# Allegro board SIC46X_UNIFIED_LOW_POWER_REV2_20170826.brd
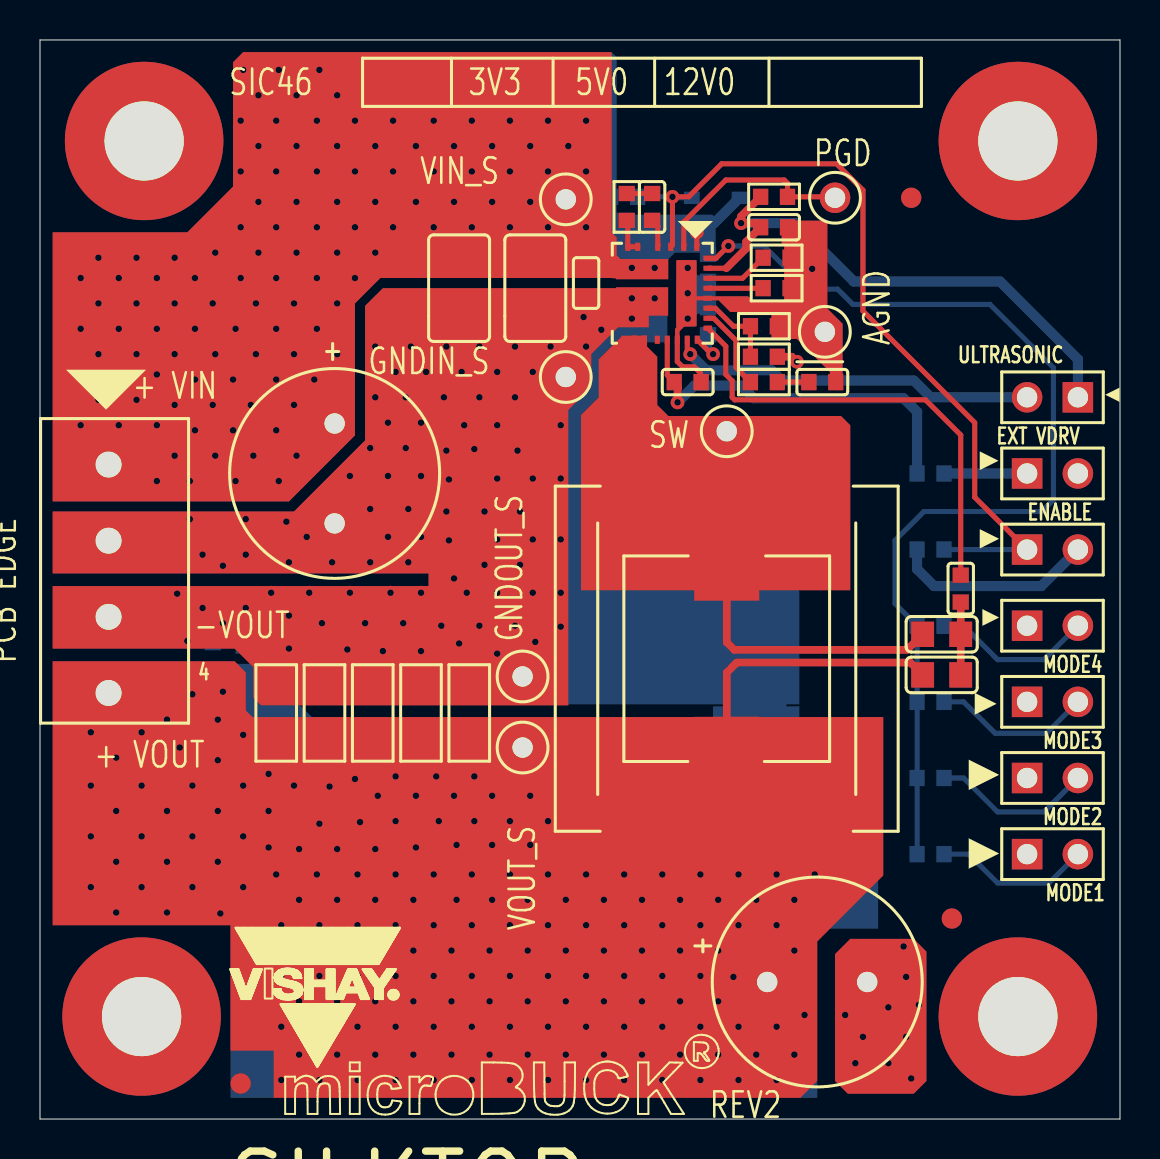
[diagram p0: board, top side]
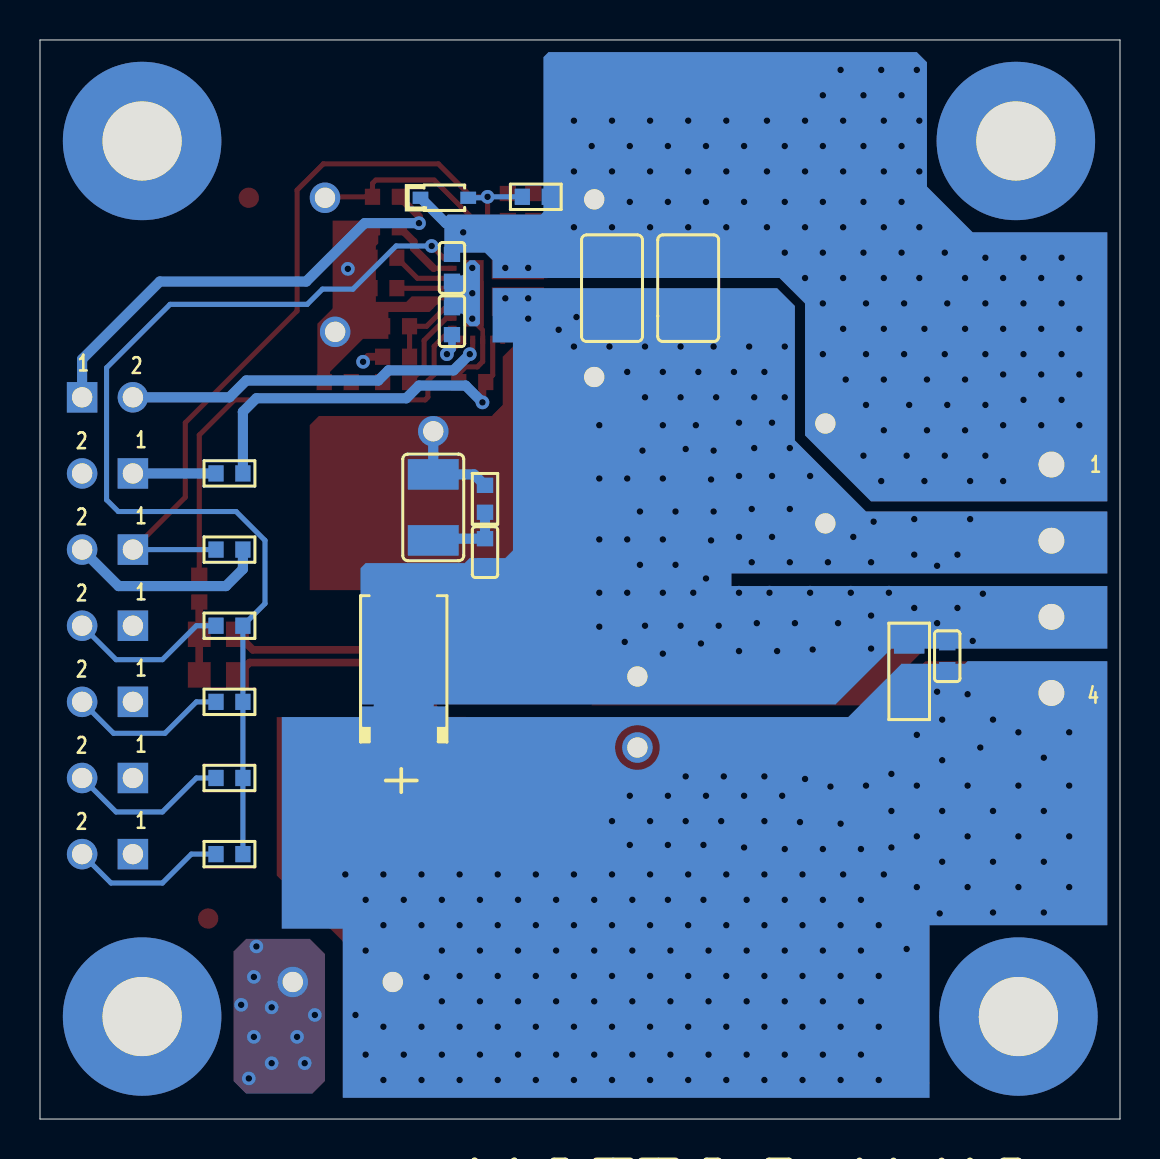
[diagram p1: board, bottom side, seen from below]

Outline 54 x 54 mm; copper layers: TOP, INNER_LAYER2, INNER_LAYER3, BOTTOM. Coordinates in mm from the lower left corner of the outline.
Outline path: 0,54 0,0 54,0 54,54 0,54

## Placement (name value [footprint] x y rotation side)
C1  0.1uF  [C0603]  30.61 45.64 270 top
C2  0.1uF  [C0603]  33.4 42.59 270 bottom
C3  1uF  [C0603]  36.7 44.63 180 top
C4  2.2uF  [C1210]  21.59 41.58 90 bottom
C5  2.2uF  [C1210]  24.77 41.58 90 top
C6  2.2uF  [C1210]  20.95 41.58 90 top
C7  2.2uF  [C1210]  25.4 41.58 90 bottom
C8  0.1uF  [C0603]  27.3 41.83 270 top
C9  1nF  [C0603]  39.12 36.88 180 top
C10  22nF  [C0603]  33.4 39.93 90 bottom
C11  4.7uF  [C0603]  32.38 36.88 180 top
C12  2.2nF  [C0603]  46.04 26.54 270 top
C13  22nF  [C0805]  45.09 22.23 180 top
C14  0.1uF  [C0603]  8.64 23.16 270 bottom
C15  22uF  [C1206]  19.05 20.32 270 top
C16  22uF  [C1206]  14.22 20.32 270 top
C17  22uF  [C1206]  10.54 22.4 270 bottom
C18  22uF  [C1206]  21.46 20.32 270 top
C19  22uF  [C1206]  11.81 20.32 270 top
C20  22uF  [C1206]  16.64 20.32 270 top
C21  DNP  [C0603]  31.75 28.37 270 bottom
C22  100uF 63V  [MAL215058101E3]  14.73 32.31 270 top
C23  470u, 2V  [T_D27_7343]  35.81 22.53 90 bottom
C24  100uF 63V  [MAL215058101E3]  38.86 6.86 0 top
D1  DNP  [BZX384C3V3]  33.78 46.1 0 bottom
J1  JUMPER  [22-28-4023]  49.35 13.26 0 top
J2  JUMPER  [22-28-4023]  49.35 17.07 0 top
J3  JUMPER  [22-28-4023]  49.35 20.88 0 top
J4  JUMPER  [22-28-4023]  49.35 24.69 0 top
J5  CON4  [20020327-D041B01LF]  3.43 32.75 270 top
J6  PGD  [5002]  39.75 46.1 0 top
J7  EN  [22-28-4023]  49.35 32.31 0 top
J8  JUMPER  [22-28-4023]  51.89 36.12 180 top
J9  EN  [22-28-4023]  49.35 28.5 0 top
J10  GND  [5002]  39.24 39.39 0 top
L1  DNP  [IHLP-4040]  34.34 23.04 90 top
L2  4.7uH  [IHLP-5050]  34.34 23.04 90 top
L3  DNP  [IHLP-6767]  34.34 23.04 90 top
NOREF  -  []  0.03 42.45 0 top
NOREF#2  -  []  4.51 -8.21 0 top
NOREF#3  -  []  117.09 -44.06 0 top
NOREF#4  -  []  58.78 -20.91 90 top
NOREF#5  -  []  54 0 90 top
NOREF#6  -  []  182.52 -46.31 90 top
NOREF#7  -  []  107.08 -20.91 90 top
NOREF#8  -  []  161.42 70.03 0 top
NOREF#9  -  []  56.01 70.03 0 top
NOREF#10  -  []  10.86 -32.97 0 top
NOREF#11  -  []  10.86 41.32 0 top
NOREF#12  -  []  161.42 70.03 90 top
NOREF#13  -  []  21.21 -21.41 90 top
NOREF#14  -  []  68.98 71.53 90 top
NOREF#15  -  []  0 54 0 top
NOREF#16  -  []  26.86 -26.06 90 top
NOREF#17  -  []  133.48 70.03 0 top
NOREF#18  -  []  17.21 -8.21 0 top
NOREF#19  -  []  -1.14 48.24 0 top
NOREF#20  -  []  10.86 16.56 0 top
NOREF#21  -  []  119.33 -10.49 0 top
NOREF#22  -  []  3.43 28.94 90 top
NOREF#23  -  []  68.98 73.03 0 top
NOREF#24  -  []  134.22 -28.53 90 top
NOREF#25  -  []  198.91 -27.76 0 top
NOREF#26  -  [unnamed#2]  43.56 46.1 0 top
NOREF#27  -  []  -1.14 -26.06 0 top
NOREF#28  -  []  132.48 73.03 0 top
NOREF#29  -  []  147.45 70.03 0 top
NOREF#30  -  []  146.45 71.53 90 top
NOREF#31  -  []  17.21 16.56 0 top
NOREF#32  -  []  69.98 70.03 0 top
NOREF#33  -  []  182.52 -31.07 90 top
NOREF#34  -  []  4.51 16.56 0 top
NOREF#35  -  []  118.49 -0.84 90 top
NOREF#36  -  []  56.01 70.03 90 top
NOREF#37  -  []  -1.14 23.47 0 top
NOREF#38  -  []  21.21 28.12 90 top
NOREF#39  -  []  26.86 23.47 90 top
NOREF#40  -  []  133.48 70.03 90 top
NOREF#41  -  []  134.22 -46.31 90 top
NOREF#42  -  []  15.27 35.05 90 top
NOREF#43  -  []  69.98 70.03 90 top
NOREF#44  -  []  107.08 -28.53 90 top
NOREF#45  -  []  -1.14 -1.29 0 top
NOREF#46  -  []  160.42 73.03 0 top
NOREF#47  -  []  4.51 41.32 0 top
NOREF#48  -  []  56.83 15.65 0 top
NOREF#49  -  []  146.45 73.03 0 top
NOREF#50  -  []  58.78 -31.07 90 top
NOREF#51  -  []  134.22 -28.53 90 top
NOREF#52  -  [unnamed#2]  5.08 5.13 0 top
NOREF#53  -  []  132.48 71.53 90 top
NOREF#54  -  [unnamed#2]  5.21 48.94 0 top
NOREF#55  -  []  107.08 -3.13 90 top
NOREF#56  -  []  107.08 -38.69 90 top
NOREF#57  -  []  21.21 52.89 90 top
NOREF#58  -  []  17.21 41.32 0 top
NOREF#59  -  []  147.45 70.03 90 top
NOREF#60  -  []  107.08 -13.29 90 top
NOREF#61  -  []  21.21 -46.17 90 top
NOREF#62  -  []  134.22 -13.29 90 top
NOREF#63  -  [unnamed#2]  48.9 5.13 0 top
NOREF#64  -  []  55.01 71.53 90 top
NOREF#65  -  []  58.78 -46.31 0 top
NOREF#66  -  []  182.52 -20.91 90 top
NOREF#67  -  []  26.86 -1.29 90 top
NOREF#68  -  []  114.81 -1.72 0 top
NOREF#69  -  []  118.15 -13.87 0 top
NOREF#70  -  []  -69.09 -66.37 0 top
NOREF#71  -  []  3.43 32.75 90 top
NOREF#72  -  []  10.86 66.09 0 top
NOREF#73  -  []  134.22 -20.91 90 top
NOREF#74  -  []  17.21 66.09 0 top
NOREF#75  -  []  -37.59 -32.57 0 top
NOREF#76  -  []  17.21 -32.97 0 top
NOREF#77  -  []  58.78 -46.31 90 top
NOREF#78  -  []  4.51 66.09 0 top
NOREF#79  -  []  193.14 -38.2 0 top
NOREF#80  -  [unnamed#2]  45.59 10.03 0 top
NOREF#81  -  []  62.61 26.08 0 top
NOREF#82  -  []  0.03 35.05 0 top
NOREF#83  -  [unnamed#2]  48.9 48.94 0 top
NOREF#84  -  []  4.51 -32.97 0 top
NOREF#85  -  []  10.86 -8.21 0 top
NOREF#86  -  []  26.86 -50.82 90 top
NOREF#87  -  []  120.78 -43.18 90 top
NOREF#88  -  []  26.86 48.24 90 top
NOREF#89  -  []  160.42 71.53 90 top
NOREF#90  -  []  107.08 -20.91 90 top
NOREF#91  -  []  -1.14 -50.82 0 top
NOREF#92  -  []  55.01 73.03 0 top
NOREF#93  -  []  134.22 -38.69 90 top
NOREF#94  -  []  134.22 4.49 0 top
NOREF#95  -  []  21.21 3.36 90 top
NOREF#96  -  [unnamed#2]  10.03 1.78 0 top
R1  102K  [R0603]  36.7 46.15 180 top
R2  3.3  [R0603]  29.34 45.64 90 top
R3  560K  [R0603]  29.21 46.15 0 bottom
R4  53.6K  [R0603]  36.83 43.1 180 top
R5  2K  [R0603]  44.53 13.26 0 bottom
R6  301K  [R0603]  44.53 17.07 0 bottom
R7  499K  [R0603]  44.53 20.88 0 bottom
R8  1M  [R0603]  44.53 24.69 0 bottom
R9  53.6K  [R0603]  36.83 41.58 180 top
R10  10K  [R0603]  36.2 39.67 180 top
R11  19.6K  [R0603]  36.2 36.88 180 top
R12  52.3K  [R0603]  36.2 38.15 0 top
R14  DNP  [R0603]  44.53 32.31 180 bottom
R15  DNP  [R0805]  45.09 24.26 180 top
R16  DNP  [R0603]  31.75 31.04 270 bottom
R16A  DNP  [R1210]  34.34 30.61 270 bottom
R17  DNP  [R0603]  44.53 28.5 0 bottom
TP1  test point  [5002]  26.29 46.02 0 top
TP2  test point  [5002]  26.29 37.13 0 top
TP3  test point  [5002]  24.13 18.59 0 top
TP4  test point  [5002]  24.13 22.15 90 top
TP11  5002  [PAD040_060_SQ]  34.34 34.42 0 top
U1  SiC46X  [5MMX5MM]  31.11 41.32 270 top

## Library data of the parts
C1-C21 = CAP NP
C22 C24 = CAP POL
C23 = CAP, TA-P,V,470u, 2V_0: User Part Number: PN; Tolerance: TOL
D1 = DIODE ZENER
J1-J4 J8 = JUMPER
J5 = HEADER 4
J6 J10 = HEADER 1
J7 J9 = HEADER 2
L1-L3 = IND
R1-R12 R14-R16 R16A R17 = RESISTOR
TP1-TP4 = TEST POINT
TP11 = TP_0
U1 = SiC462CD-T1-GE3_32

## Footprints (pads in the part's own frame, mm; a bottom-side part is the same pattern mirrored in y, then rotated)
5MMX5MM
  rect 0.406x0.254 smd: 1(-2.325,1.725) 2(-2.325,1.075) 3(-2.325,0.425) 4(-2.325,-0.225) 5(-2.325,-1.225) 6(-2.325,-1.725) 13(2.325,-1.4) 14(2.325,-0.9) 15(2.325,-0.25) 16(2.325,0.25) 17(2.325,0.75) 18(2.325,1.25) 19(2.325,1.75)
  rect 0.254x0.432 smd: 7(-1.525,-2.275) 8(-0.875,-2.275) 9(0.25,-2.275) 10(0.75,-2.275) 11(1.25,-2.275) 20(1.75,2.275) 21(1.25,2.275) 22(0.75,2.275) 23(0.25,2.275) 24(-0.25,2.275) 25(-0.75,2.275) 26(-1.25,2.275) 27(-1.75,2.275)
  rect 0.406x1.27 smd: 12(2.325,-1.408)
  rect 3.302x1.016 smd: 28(0,1.208)
  rect 1.016x2.616 smd: 29(-1.208,-1.008)
  custom 0.5x0.5 smd: 30(0.7,-1.008)
22-28-4023
  rect 1.524x1.524 hole 1.016: 1(0,0)
  round 1.524 hole 1.016: 2(2.54,0)
5002
  round 1.524 hole 1.016: 1(0,0)
20020327-D041B01LF
  rect 2.057x2.057 hole 1.295: 1(0,0)
  round 2.057 hole 1.295: 2(3.81,0) 3(7.62,0) 4(11.43,0)
BZX384C3V3
  rect 0.787x0.61 smd: 1(1.194,0) 2(-1.194,0)
C0603
  rect 0.762x0.813 smd: 1(-0.673,0) 2(0.673,0)
C0805
  rect 1.143x1.27 smd: 1(-0.953,0) 2(0.953,0)
C1206
  rect 1.27x1.524 smd: 1(-1.524,0) 2(1.524,0)
C1210
  rect 1.524x2.54 smd: 1(-1.651,0) 2(1.651,0)
IHLP-4040
  rect 3.124x3.251 smd: 1(-4.47,0) 2(4.47,0)
IHLP-5050
  rect 3.175x3.251 smd: 1(-5.715,0) 2(5.715,0)
IHLP-6767
  rect 3.81x12.319 smd: 1(-8.077,0) 2(8.077,0)
MAL215058101E3
  rect 1.524x1.524 hole 1.016: 1(-2.5,0)
  round 1.524 hole 1.016: 2(2.5,0)
PAD040_060_SQ
  round 1.524 hole 1.016: 1(0,0)
R0603
  rect 0.762x0.813 smd: 1(-0.673,0) 2(0.673,0)
R0805
  rect 1.143x1.27 smd: 1(-0.953,0) 2(0.953,0)
R1210
  rect 1.524x2.54 smd: 1(-1.651,0) 2(1.651,0)
T_D27_7343
  rect 2.134x2.997 smd: 1(-3.429,0) 3(3.429,0)
  custom 1.079x1.079 smd: 2(0,0)
unnamed#2
  round 1.016 smd: 1(0,0)

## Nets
GND: C4.1 C5.1 C6.1 C7.1 C8.2 C14.1 C15.1 C16.1 C17.1 C18.1 C19.1 C20.1 C21.2 C22.2 C23.2 C23.3 C24.2 J5.2 J5.3 J7.2 TP2.1 TP4.1 U1.9(PGND1) U1.10(PGND2) U1.11(PGND3) U1.30(PGND-PAD)
GND_SIGNAL: C2.2 C3.1 C9.1 C10.2 C11.1 J1.1 J2.1 J3.1 J4.1 J9.2 J10.1 R4.1 R9.1 R10.1 R17.1 U1.17(CDRV_RTN) U1.23(AGND) U1.28(AGND-PAD)
VDD: C3.2 J8.1 R1.2 U1.26(VDD)
VIN: C2.1 C4.2 C5.2 C6.2 C7.2 C8.1 C22.1 D1.1(CATHODE) J5.1 R3.1 TP1.1 U1.1(VCIN) U1.7(VIN1) U1.8(VIN2) U1.29(VIN-PAD)
BOOT: C1.2 U1.4(BOOT)
COMP: R11.2 U1.21(COMP)
ENABLE: D1.2(ANODE) J9.1 R3.2 R17.2 U1.3(EN)
FSW: R9.2 U1.24(FSW)
ILIM: R4.2 U1.25(ILIMIT)
MODE: R5.1 R6.1 R7.1 R8.1 U1.27(MODE)
PGD: J6.1 R1.1 U1.2(PGOOD)
SS: C10.1 U1.19(SS)
SW: L1.2(B) L2.2(B) L3.2(B) R15.2 R16.1 R16A.1 TP11.1 U1.12(SW1) U1.13(SW2) U1.14(SW3)
ULTRASONIC: J8.2 U1.18(ULTRASONIC)
VDRV: C11.2 R14.2 U1.16(VDRV)
VDRV_IN: J7.1 R14.1
VFB: R10.2 R12.1 U1.22(VFB)
VO: C13.2 C14.2 C15.2 C16.2 C17.2 C18.2 C19.2 C20.2 C23.1 C24.1 J5.4 L1.1(A) L2.1(A) L3.1(A) R12.2 TP3.1
N16770186: R2.1 U1.5(PHASE1) U1.6(PHASE2)
N16770229: C1.1 R2.2
N16771868: C9.2 R11.1
N16772198: J1.2 R5.2
N16772202: J2.2 R6.2
N16772206: J3.2 R7.2
N16812890: C21.1 R16.2 R16A.2
N16829136: J4.2 R8.2
N16842327: C12.1 U1.20(VSNS)
N16874863: C12.2 C13.1 R15.1

Pads without a net: NOREF#26 1; NOREF#52 1; NOREF#54 1; NOREF#63 1; NOREF#80 1; NOREF#83 1; NOREF#96 1; U1 15

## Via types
v1: diameter 0.686, hole 0.33, TOP to BOTTOM, 418 vias

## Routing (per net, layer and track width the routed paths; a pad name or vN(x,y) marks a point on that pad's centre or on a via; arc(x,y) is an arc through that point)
GND:
  vias: v1(6.86,26.29) v1(7.37,23.92) v1(7.49,30.02) v1(8.13,28.24) v1(8.13,25.58) v1(9.14,27.69) v1(9.14,24.81) v1(10.29,30.02) v1(10.29,28.24) v1(10.29,25.58) v1(11.56,26.34) v1(12.32,29.89) v1(12.45,27.86) v1(12.45,25.19) v1(12.45,23.54) v1(13.34,29.13) v1(13.46,26.34) v1(14.1,24.81) v1(14.61,27.86) v1(15.37,23.5) v1(15.49,32.18) v1(15.49,26.34) v1(16.26,24.81) v1(16.51,33.58) v1(16.51,30.53) v1(16.51,27.86) v1(16.76,38.66) v1(16.76,36.12) v1(17.14,23.42) v1(17.4,34.85) v1(17.4,32.18) v1(17.4,29.13) v1(17.53,26.34) v1(17.78,37.39) v1(18.16,24.81) v1(18.29,36.12) v1(18.29,33.58) v1(18.41,30.53) v1(18.41,27.86) v1(18.54,38.66) v1(19.05,34.85) v1(19.05,32.18) v1(19.05,29.13) v1(19.05,26.34) v1(19.05,23.42) v1(19.3,37.39) v1(20.07,24.69) v1(20.19,36.12) v1(20.32,38.66) v1(20.32,33.45) v1(20.32,30.4) v1(20.45,32) v1(20.45,28.96) v1(20.7,27.05) v1(20.95,23.8) v1(21.08,37.39) v1(21.21,34.72) v1(21.34,26.34) v1(21.72,33.53) v1(21.97,38.66) v1(21.97,36.12) v1(21.97,24.69) v1(22.23,30.4) v1(22.23,27.73) v1(22.86,37.39) v1(22.86,34.72) v1(22.86,32.05) v1(22.86,29) v1(22.86,26.34) v1(22.86,23.29) v1(23.75,38.66) v1(23.75,36.12) v1(23.75,24.69) v1(23.88,33.45) v1(24,30.4) v1(24,27.73) v1(24.64,37.39) v1(24.64,32.05) v1(24.64,29) v1(24.64,26.34) v1(24.77,23.88) v1(25.53,38.66) v1(26.04,34.72) v1(26.04,32.05) v1(26.04,29) v1(26.04,26.34) v1(26.04,24.64) v1(27.18,40.13) v1(27.3,38.66) v1(28.07,39.5) v1(29.59,41.07) v1(29.59,40.05) v1(30.73,41.07) v1(40.26,5.21) v1(40.77,2.79) v1(41.15,4.11) v1(42.42,5.59) v1(42.42,2.79) v1(43.18,8.64) v1(43.31,7.11) v1(43.31,4.11) v1(43.56,2.03) v1(43.94,5.71)
GND_SIGNAL: length 13.1
  TOP w0.254: U1.17 31.87,37.91 32.13,37.64 32.72,37.64 33.02,37.34 33.02,36.92 C11.1
  BOTTOM w0.508: J9.2 50.07,26.67 44.7,26.67 43.86,27.52 R17.1
  vias: v1(32.38,42.59) v1(32.38,41.32) v1(32.38,40.05) v1(38.61,42.55)
VDD: length 28
  TOP w0.254: 34.32,42.57 U1.26
  TOP w0.381: 34.32,42.57 35.31,43.56 35.31,43.9 C3.2 35.82,44.83 v1(35.05,44.83) 35.05,45.17 R1.2
  BOTTOM w0.508: J8.1 51.89,38.02 48.01,41.91 40.69,41.91 37.77,44.83 v1(35.05,44.83)
VIN: length 2.7
  TOP w0.254: U1.1 v1(32.84,44.37)
  BOTTOM w0.508: D1.1 33.71,44.83 33.53,44.83
  vias: v1(2.03,42.09) v1(2.03,39.55) v1(2.03,37.26) v1(2.03,34.72) v1(2.92,43.1) v1(2.92,40.82) v1(2.92,38.28) v1(2.92,35.99) v1(3.94,42.09) v1(3.94,39.55) v1(3.94,37.26) v1(3.94,34.72) v1(4.83,43.1) v1(4.83,40.82) v1(4.83,38.28) v1(4.83,35.99) v1(5.84,42.09) v1(5.84,39.55) v1(5.84,37.26) v1(5.84,34.72) v1(5.84,31.93) v1(6.73,43.1) v1(6.73,40.82) v1(6.73,38.28) v1(6.73,35.74) v1(6.73,33.2) v1(7.49,31.93) v1(7.75,42.09) v1(7.75,39.55) v1(7.75,37.01) v1(7.75,34.47) v1(8.64,40.82) v1(8.64,35.74) v1(8.76,43.36) v1(8.76,38.28) v1(8.76,33.2) v1(9.65,37.01) v1(9.65,34.47) v1(9.78,39.55) v1(9.78,31.93) v1(10.03,49.96) v1(10.03,47.42) v1(10.03,44.63) v1(10.03,42.09) v1(10.16,52.5) v1(10.54,35.74) v1(10.67,33.2) v1(10.79,40.82) v1(10.79,38.28) v1(10.92,51.23) v1(10.92,48.69) v1(10.92,45.9) v1(10.92,43.36) v1(11.81,49.96) v1(11.81,47.42) v1(11.81,44.63) v1(11.81,42.09) v1(11.81,39.55) v1(11.81,37.01) v1(11.81,34.47) v1(11.94,52.5) v1(11.94,31.93) v1(12.7,40.82) v1(12.7,38.28) v1(12.7,35.74) v1(12.83,51.23) v1(12.83,48.69) v1(12.83,45.9) v1(12.83,43.36) v1(12.83,33.2) v1(13.72,37.01) v1(13.84,49.96) v1(13.84,47.42) v1(13.84,44.63) v1(13.84,42.09) v1(13.84,39.55) v1(13.97,52.5) v1(14.86,51.23) v1(14.86,48.69) v1(14.86,45.9) v1(14.86,43.36) v1(14.86,40.82) v1(14.86,38.28) v1(15.75,49.96) v1(15.75,47.42) v1(15.75,44.63) v1(15.75,42.09) v1(16.76,48.69) v1(16.76,45.9) v1(16.76,43.36) v1(17.65,49.96) v1(17.65,47.42) v1(17.65,44.63) v1(18.8,48.69) v1(18.8,45.9) v1(19.68,49.96) v1(19.68,47.42) v1(19.68,44.63) v1(20.7,48.69) v1(20.7,45.9) v1(21.59,49.96) v1(21.59,47.42) v1(21.59,44.63) v1(22.61,48.69) v1(22.61,45.9) v1(23.5,49.96) v1(23.5,47.42) v1(23.5,44.63) v1(24.51,48.69) v1(24.51,45.9) v1(25.4,49.96) v1(25.4,47.42) v1(25.4,44.63) v1(26.42,48.69) v1(27.3,49.96) v1(27.3,47.42) v1(27.3,44.63) v1(29.59,42.59) v1(30.73,42.59)
BOOT: length 1.4
  TOP w0.254: C1.2 30.89,44.69 U1.4
COMP: length 4.3
  TOP w0.254: U1.21 33.69,40.07 34.8,38.96 34.8,37.6 R11.2
ENABLE: length 41.6
  TOP w0.254: U1.3 31.62,43.73 v1(31.62,46.15) 32.43,46.15 34.08,47.8 39.83,47.8 41.15,46.48 41.15,40.43 46.74,34.85 46.74,31.11 J9.1
  BOTTOM w0.254: D1.2 31.67,46.1 v1(31.62,46.15) R3.2 ; J9.1 R17.2
FSW: length 2.8
  TOP w0.254: R9.2 36.15,41.57 U1.24
ILIM: length 3.2
  TOP w0.254: R4.2 35.13,42.07 U1.25
MODE: length 51.6
  TOP w0.254: U1.27 33.8,43.07 v1(34.42,43.69)
  BOTTOM w0.254: R5.1 R6.1 R7.1 R8.1 42.75,25.79 42.75,28.96 44.2,30.4 50.09,30.4 50.67,30.99 50.67,37.59 47.5,40.77 40.64,40.77 39.88,41.53 38.35,41.53 36.2,43.69 v1(34.42,43.69)
PGD: length 10.4
  TOP w0.254: U1.2 32.19,44.89 34.29,46.99 37.21,46.99 37.38,46.82 R1.1 39.7,46.15 J6.1
SS: length 2.2
  TOP w0.254: U1.19 33.59,38.28 v1(33.66,38.28)
  BOTTOM w0.381: v1(33.66,38.28) 33.4,38.53 C10.1
SW: length 22.5
  TOP w0.381: L3.2 L2.2 L1.2 34.34,23.86 34.72,23.48 43.36,23.48 R15.2
  BOTTOM w0.508: TP11.1 R16A.1 32.3,32.26 R16.1
ULTRASONIC: length 18.5
  TOP w0.254: v1(32.51,38.28) 32.37,38.42 U1.18
  BOTTOM w0.508: v1(32.51,38.28) 33.32,37.47 36.58,37.47 37.08,36.96 43.69,36.96 44.53,36.12 J8.2
VDRV: length 19.3
  TOP w0.254: U1.16 31.37,37.22 C11.2
  TOP w0.381: v1(31.88,35.86) 31.88,36.71 C11.2
  BOTTOM w0.508: R14.2 43.86,35.39 43.18,36.07 35.69,36.07 35.05,36.7 32.72,36.7 v1(31.88,35.86)
VDRV_IN: length 4.2
  BOTTOM w0.508: J7.1 R14.1
VFB: length 4
  TOP w0.254: U1.22 33.77,40.57 34.67,39.67 R10.2 R12.1
VO: length 84
  TOP w0.381: v1(37.85,37.89) 37.59,38.15 R12.2 ; C13.2 43.51,22.84 34.84,22.84 34.34,22.34 L1.1 L2.1 L3.1
  INNER_LAYER3 w0.508: 3.43,21.32 4.46,22.35 11.94,22.35 14.1,20.19 23.62,20.19 24.13,19.68 TP3.1 25.32,17.4 42.29,17.4 43.43,18.54 43.43,32.31 v1(37.85,37.89)
  vias: v1(2.54,19.35) v1(2.54,16.69) v1(2.54,14.15) v1(2.54,11.61) v1(3.81,18.08) v1(3.81,15.42) v1(3.81,12.88) v1(3.81,10.34) v1(5.08,19.35) v1(5.08,16.69) v1(5.08,14.15) v1(5.08,11.61) v1(6.35,19.99) v1(6.35,15.42) v1(6.35,12.88) v1(6.35,10.34) v1(6.99,18.59) v1(7.62,21.26) v1(7.62,16.69) v1(7.62,14.15) v1(7.62,11.61) v1(8.89,19.99) v1(8.89,17.96) v1(8.89,15.42) v1(8.89,12.88) v1(9.02,10.29) v1(9.14,21.38) v1(10.16,19.23) v1(10.16,16.69) v1(10.16,14.15) v1(10.16,11.61) v1(10.67,8.51) v1(11.43,17.27) v1(11.43,15.42) v1(11.43,13.59) v1(11.81,12.24) v1(12.06,9.7) v1(12.06,7.16) v1(12.06,4.62) v1(12.06,1.95) v1(12.7,16.69) v1(12.95,13.51) v1(12.95,10.97) v1(12.95,8.43) v1(12.95,5.89) v1(12.95,3.22) v1(13.84,12.24) v1(13.97,14.78) v1(13.97,9.7) v1(13.97,7.16) v1(13.97,4.62) v1(13.97,1.95) v1(14.48,16.64) v1(14.86,13.51) v1(14.86,10.97) v1(14.86,8.43) v1(14.86,5.89) v1(14.86,3.22) v1(15.75,17.02) v1(15.88,12.24) v1(15.88,9.7) v1(15.88,7.16) v1(15.88,4.62) v1(15.88,1.95) v1(16,14.86) v1(16.76,13.51) v1(16.76,10.97) v1(16.76,8.43) v1(16.76,5.89) v1(16.76,3.22) v1(16.89,16.18) v1(17.78,17.14) v1(17.78,14.91) v1(17.78,12.24) v1(17.78,9.7) v1(17.78,7.16) v1(17.78,4.62) v1(17.78,1.95) v1(18.67,10.97) v1(18.67,8.43) v1(18.67,5.89) v1(18.67,3.22) v1(18.8,16.18) v1(18.8,13.59) v1(19.68,12.24) v1(19.68,9.7) v1(19.68,7.16) v1(19.68,4.62) v1(19.68,1.95) v1(19.81,17.14) v1(19.94,14.91) v1(20.57,8.43) v1(20.57,5.89) v1(20.57,3.22) v1(20.7,16.18) v1(20.83,13.72) v1(20.83,10.97) v1(21.59,12.24) v1(21.59,9.7) v1(21.59,7.16) v1(21.59,4.62) v1(21.59,1.95) v1(21.72,17.14) v1(21.72,14.91) v1(22.48,8.43) v1(22.48,5.89) v1(22.48,3.22) v1(22.61,16.18) v1(22.61,13.72) v1(22.61,10.97) v1(23.5,14.91) v1(23.5,12.24) v1(23.5,9.7) v1(23.5,7.16) v1(23.5,4.62) v1(23.5,1.95) v1(24.38,10.97) v1(24.38,8.43) v1(24.38,5.89) v1(24.38,3.22) v1(24.51,16.18) v1(24.51,13.72) v1(25.4,14.91) v1(25.4,12.24) v1(25.4,9.7) v1(25.4,7.16) v1(25.4,4.62) v1(25.4,1.95) v1(26.29,10.97) v1(26.29,8.43) v1(26.29,5.89) v1(26.29,3.22) v1(27.3,12.24) v1(27.3,9.7) v1(27.3,7.16) v1(27.3,4.62) v1(27.3,1.95) v1(28.19,10.97) v1(28.19,8.43) v1(28.19,5.89) v1(28.19,3.22) v1(29.21,12.24) v1(29.21,9.7) v1(29.21,7.16) v1(29.21,4.62) v1(29.21,1.95) v1(30.1,10.97) v1(30.1,8.43) v1(30.1,5.89) v1(30.1,3.22) v1(31.11,12.24) v1(31.11,9.7) v1(31.11,7.16) v1(31.11,4.62) v1(31.11,1.95) v1(32,10.97) v1(32,8.43) v1(32,5.89) v1(32,3.22) v1(33.02,12.24) v1(33.02,9.7) v1(33.02,7.16) v1(33.02,4.62) v1(33.02,1.95) v1(33.91,10.97) v1(33.91,8.43) v1(33.91,5.89) v1(33.91,3.22) v1(34.67,7.11) v1(34.92,12.24) v1(34.92,9.7) v1(34.92,4.62) v1(34.92,1.95) v1(35.81,10.97) v1(35.81,3.22) v1(36.83,12.24) v1(36.83,9.7) v1(36.83,4.62) v1(36.83,1.95) v1(37.72,10.97) v1(37.72,8.43) v1(37.72,3.22) v1(38.23,5.21) v1(38.73,12.24)
N16770186: length 1.8
  TOP w0.254: R2.1 29.39,44.92 U1.6 U1.5
N16770229: length 1.3
  TOP w0.254: C1.1 R2.2
N16771868: length 1.6
  TOP w0.254: C9.2 R11.1
N16772198: length 7.9
  BOTTOM w0.254: R5.2 46.43,13.26 47.88,11.81 50.45,11.81 J1.2
N16772202: length 8.1
  BOTTOM w0.254: R6.2 46.18,17.07 47.88,15.37 50.2,15.37 J2.2
N16772206: length 8
  BOTTOM w0.254: J3.2 50.32,19.3 47.75,19.3 46.18,20.88 R7.2
N16812890: length 3.9
  BOTTOM w0.508: R16A.2 34.25,29.04 C21.1 R16.2
N16829136: length 8.1
  BOTTOM w0.254: J4.2 50.2,22.99 47.88,22.99 46.18,24.69 R8.2
N16842327: length 23.2
  TOP w0.254: U1.20 34.29,38.67 34.29,37.26 34.61,36.94 34.61,36.12 34.73,35.99 44.27,35.99 46.04,34.23 C12.1
N16874863: length 3.6
  TOP w0.381: C13.1 R15.1 C12.2

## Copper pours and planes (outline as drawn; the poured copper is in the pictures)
GND on TOP (solid shape): 44.32,8.38 44.32,1.91 43.69,1.27 40.39,1.27 39.75,1.91 39.75,8.26 40.51,9.02 43.69,9.02
GND on TOP (solid shape): 31.37,40.31 30.35,40.31 30.35,39.67 28.96,39.67 27.56,38.28 27.56,36.62 26.42,35.48 26.42,20.7 11.05,20.7 10.67,21.08 10.67,22.61 9.73,23.54 0.64,23.54 0.64,26.67 19.43,26.67 19.43,27.3 0.64,27.3 0.64,30.4 12.7,30.4 16.26,33.96 16.26,40.69 17.14,41.58 31.37,41.58
GND on BOTTOM (solid shape): 31.37,38.86 30.35,38.86 30.35,28.45 30.73,28.07 32.51,28.07 32.77,27.81 37.72,27.81 37.97,27.56 37.97,20.75 14.22,20.75 11.43,23.54 0.64,23.54 0.64,26.67 19.43,26.67 19.43,27.3 0.64,27.3 0.64,30.4 12.7,30.4 16.26,33.96 16.26,40.69 17.14,41.58 31.37,41.58
GND on BOTTOM: 39.75,8.26 39.75,1.91 40.39,1.27 43.69,1.27 44.32,1.91 44.32,8.38 43.69,9.02 40.51,9.02
GND on INNER_LAYER2: 5.84,0.64 5.84,4.83 0.64,4.83 0.64,26.67 19.43,26.67 19.43,27.3 0.64,27.3 0.64,46.61 5.71,46.61 5.71,53.36 48.77,53.36 48.77,46.61 53.37,46.61 53.37,6.1 49.66,6.1 49.66,2.92 47.62,2.92 47.62,0.64
GND on INNER_LAYER3: 4.7,0.64 4.7,4.45 0.64,4.45 0.64,26.67 19.43,26.67 19.43,27.3 0.64,27.3 0.64,46.61 5.84,46.61 5.84,53.36 48.13,53.36 48.13,46.61 53.37,46.61 53.37,6.1 47.62,6.1 47.62,0.64
GND_SIGNAL on TOP (solid shape): 32.77,39.67 32.23,39.67 31.98,39.42 31.98,38.84 31.95,38.81 31.75,38.81 31.75,39.55 31.83,39.62 31.83,41.91 32.77,41.91
GND_SIGNAL on TOP (solid shape): 39.37,40.56 40.13,39.8 40.13,36.5 39.5,36.5 39.5,37.39 37.85,39.04 36.58,39.04 36.58,40.39 34.52,40.39 33.93,40.97 32.77,40.97 32.77,39.67 31.88,39.67 31.88,42.97 32.77,42.97 32.77,41.17 35.41,41.17 35.69,40.89 37.21,40.89 37.21,43.69 37.08,43.81 37.08,44.96 39.37,44.96
GND_SIGNAL on BOTTOM (solid shape): 32.77,42.72 32.77,42.34 32.89,42.21 33.78,42.21 33.78,40.31 32.89,40.31 32.77,40.18 32.77,39.93 32.51,39.67 32.13,39.67 32,39.8 32,42.72 32.26,42.97 32.51,42.97
GND_SIGNAL on INNER_LAYER2: 53.34,42.97 53.34,11.61 42.55,11.61 42.55,35.56 31.88,35.56 31.24,36.2 31.24,38.02 31.75,38.53 31.75,43.36 28.96,43.36 28.96,48.18 39.83,48.18 44.15,43.86 52.45,43.86
VIN on TOP (solid shape): 28.57,44.37 28.83,44.12 28.83,43.23 29.08,42.97 31.37,42.97 31.37,42.09 17.02,42.09 15.75,40.82 15.75,34.21 12.45,30.91 0.64,30.91 0.64,44.37 7.37,44.37 9.65,46.66 9.65,52.88 10.16,53.39 28.57,53.39
VIN on BOTTOM (solid shape): 28.83,53.13 28.83,45.39 28.96,45.26 33.61,45.26 33.78,45.09 33.78,42.97 33.15,42.97 33.15,43.36 31.75,43.36 31.37,42.97 31.37,42.09 17.02,42.09 15.75,40.82 15.75,34.21 12.45,30.91 0.64,30.91 0.64,44.37 7.37,44.37 9.65,46.66 9.65,52.88 10.16,53.39 28.57,53.39
VIN on INNER_LAYER3: 0.64,30.91 0.64,46.66 5.84,46.66 5.84,53.39 28.57,53.39 28.57,44.37 29.46,43.48 31.24,43.48 31.24,42.09 17.02,42.09 15.75,40.82 15.75,34.21 12.45,30.91
SW on TOP (solid shape): 30.35,38.66 30.86,38.15 30.86,35.74 31.42,35.18 40.05,35.18 40.51,34.72 40.51,26.46 27.05,26.46 27.05,35.23 27.94,36.12 27.94,38.02 29.08,39.16 30.35,39.16
VO on TOP (solid shape): 10.29,22.35 10.29,20.45 10.62,20.11 42.16,20.11 42.16,12.19 38.86,8.89 38.86,1.91 38.02,1.06 11.68,1.06 11.68,3.43 9.53,3.43 9.53,9.7 0.64,9.7 0.64,22.91 9.73,22.91
VO on BOTTOM (solid shape): outline of 89 points within 0.64,1.06 41.91,22.91
VO on INNER_LAYER3: 4.7,0.68 4.7,4.49 0.64,4.49 0.64,22.48 3.81,22.48 4.57,21.72 11.68,21.72 13.84,19.56 22.35,19.56 22.99,18.92 22.99,17.53 23.62,16.89 42.16,16.89 42.16,12.19 38.86,8.89 38.86,0.68

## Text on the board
Ref Des/Assembly Bottom: ASSEMBLY BOTTOM
Ref Des/Silkscreen Bottom: SILK BOTTOM
User.Comments: CR_1_2
Ref Des/Assembly Top: ASSEMBLY TOP
Ref Des/Silkscreen Top: ULTRASONIC | EXT VDRV | ENABLE | MODE4 | MODE3 | MODE2 | MODE1 | + VOUT | + VIN | -VOUT | SIC46 | GNDIN_S | VIN_S | 3V3 | 5V0 | SW | 12V0 | REV2 | PGD | GNDOUT_S | VOUT_S | AGND | SILKTOP
INNER_LAYER2: INNER_LAYER2
INNER_LAYER3: INNER_LAYER3
User.16: 20.LAYER STACKUP     4 LAYERS. SEE STACK-UP DETAIL. | 17.SOLDER MASK COLOR:LIGHT BLUE (OR CLOSEST) | 22.FIDUCIALS         ADD FIDUCIALS TO PRIMARY SIDES. | 23 MATERIAL:         LEAD-FREE PROCESS | 24 COLOR:            LIGHT BLUE (OR CLOSEST) | 25 COPPER THICKNESS: SEE STACK-UP DETAIL. | 18.FINISH            SOLDER MASK OVER BARE COPPER (SMOBC) WITH | HOT AIR SOLDER LAVELING (HASL). | 19.SILKSCREEN        WHITE NONCONDUCTIVE INK. | NO INK TO APPEAR ON EXPOSED COPPER SUCH AS PLATE THROUGH HOLE PADS AND | SURFACE MOUNT LANDS. INK ON SOLDER MASK COVERED PADS IS PERMISSIBLE. | 16.SOLDER MASK       TO BE IN ACCORDANCE WITH IPC-SM-840C CLASS T. | TYPE: LIQUID PHOTOIMAGEABLE. | BRAND: CIBA-GEIGY PROBIMER 52, 65M, ENTHONE ENPLATE DSR-3241 OR EQUIVALENT. | FINISH: MATTE FINISH PREFERRED. | COLOR: LIGHT BLUE (OR CLOSEST) | REGISTRATION: TO BE WITHIN +/-0.003 OF ITS RESPECTIVE OUTER CIRCUIT LAYERS. | SOLDER MASK ENCROACHMENT ONTO SMT LANDS IS INTENTIONAL | WHERE SUPPLIED DATA DOES NOT PROVIDE CLEARANCE FROM THE PAD. | 21.TOTAL THICKNESS   0.062". | 1. PART NUMBER       P/N 133-020-0002 | 2. SIDE SHOWN        PRIMARY / SIDE 1. | 14.Minimum immersion gold thickness  of 2uin - 8uin over a minimum of 118uin electroless nickel. | 3. DIMENSIONS        DECIMAL INCHES. | 4. BASE MATERIAL     LEAD-FREE PROCESS | 5. Tg                MINIMUM GLASS TRANSITTION TEMPERATURE (Tg) OF 170 DEGREES CELSIUS. | 6. FLAME CLASS       UL 94V-0 & MUST MEET REQUIREMENTS OF UL 796. | 7. MOT               MANUFACTURE MUST BE UL RECOGNIZED TO PRODUCE THIS PRODUCT SUCH THAT | IT MEETS 130 DEGREES CELSIUS MAXIMUM OPERATING TEMPERATURE (MOT). | 8. MARKINGS         THE FOLLOWING MUST BE MARKED OR ETCHED ON SIDE 2 OF PCB IN AREA SHOWN: | DATE CODE. | UL RECOGNIZED VENDOR ID UL TYPE DESIGNATION AND/OR MARKINGS WHICH REPLECT | THE SPECIFIED FLAME CLASS AND MAXIMUM OPERATING TEMPERATURE RATTINGS. | 9. PCB THICKNESS     0.62 +/-10% AS MESURED OVER METAL. | 10.BOW & TWIST       SHALL BE DETERMINED BY PHYSICAL MEASUREMENT AND PERCENTAGE | CALCULATION IN ACCORDANCE WITH IPC - TM - 650. METHOD 2.4.22. | 11.PLATING           MINIMUM COPPER THICKNESS  AFTER PROCESSING INTERNAL AND EXTERNAL LAYERS | IS PROVIDED BELOW IN THE LAYER STACKUP. | HOLE PLATING = 0.001 MIN. AVERAGE / 0.0008 ABSOLUTE MIN PLATING. | HOLE DIAMETERS SPECIFIED AFTER PLATING (SEE HOLE SCHEDULE). | 12.CONDUCTORS        FINISHED CONDUCTOR WIDTH: 0.010 REDUCED NO MORE THAN 20% OF NOMINAL. | FINISHED CONDUCTOR SPACING: 0.003 MINIMUM. | 13.ANNULAR RING      0.001 MINIMUM FOR INTERNAL ANNULAR RING. | 0.002 MINIMUM FOR EXTERNAL ANNULAR RING. | 15.When applies Gold Plating and Nickel Plating For Edge-Board Connectors and | Unless Otherwise Specified on the Fabrication Drawing. | Non-Soldered Areas Shall be Per IPC-2221 | For none functional short gold fingers it is ok to leave the plating trace | FAB NOTES:UNLESS OTHERWISE SPECIFIED.
User.28: L02_GND1
User.29: L03_VDD
User.32: L04_PWR2
User.33: L05_GND2
User.35: LAYER 1    (TOP SIDE) 1.0 OZ. | LAYER 2    INNER LAYER 2 2.0 OZ. | LAYER 3    INNER LAYER 3 2.0 OZ. | LAYER 4    (BOTTOM SIDE) 1.0 OZ. | SILKSCREEN (TOP SIDE) | SOLDERMASK (TOP SIDE) | SOLDERMASK (BOTTOM SIDE) | SILKSCREEN (BOTTOM SIDE) | .0062 +/- 10% | LAYER DETAIL | 4 LAYER
User.36: L03_VDD
User.37: L2_GND1
User.38: L3_SIG1
User.39: L4_PWR1
User.40: L5_PWR2
User.41: L6_SIG2
User.42: L7_GND2
User.45: INNER_LAYER4 | INNER_LAYER5 | FIGURE | SIZE | 13.0 | 40.0 | 51.0 | 156.0 | DRILL CHART: TOP to BOTTOM | ALL UNITS ARE IN MILS | TOLERANCE | +3.0/-13.0 | +3.0/-3.0 | PLATED | QTY | 418 | 25 | 4
